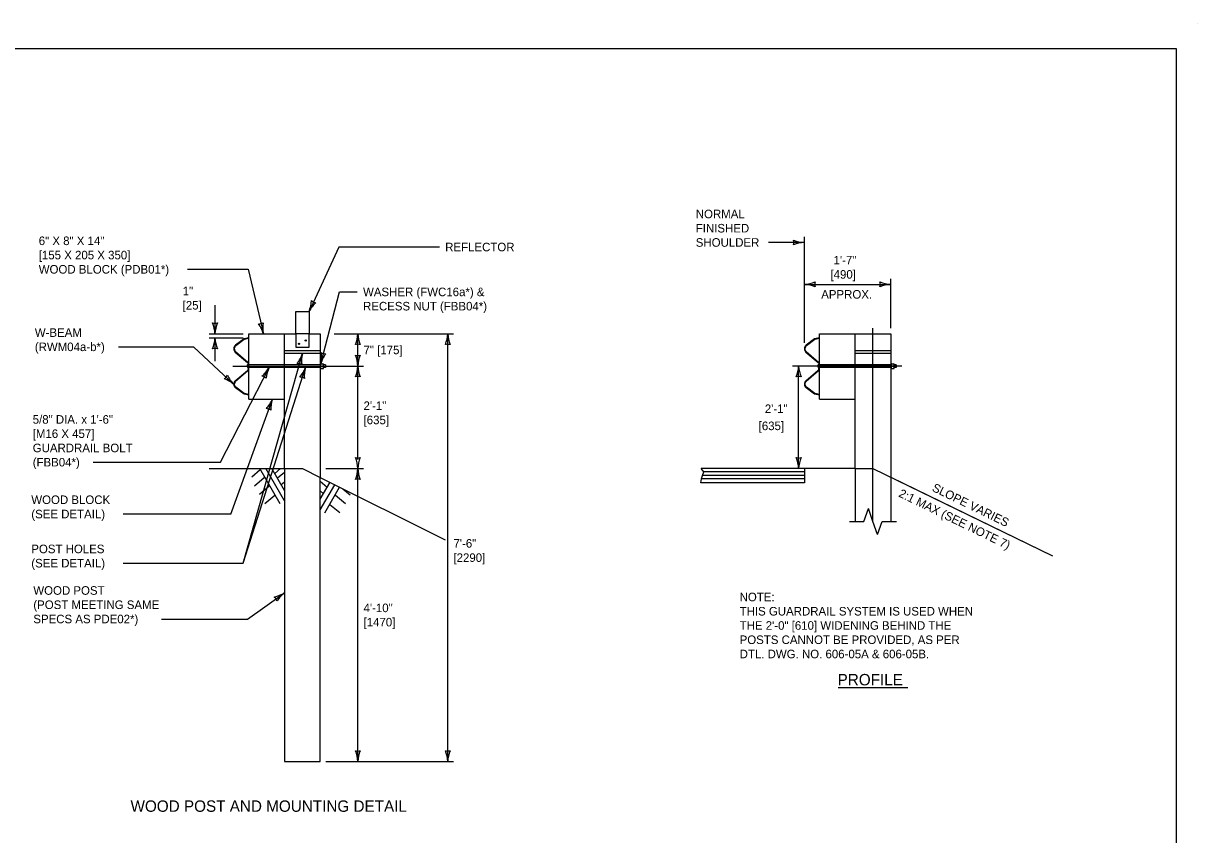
# Model space of a CAD drawing. Extents: x 49991.4 to 50021, y 49987.6 to 50011.4.
# Drawn here: x 50008.67 to 50016.9, y 49993.49 to 49999.18 of the extents above; entities that cross this region are included whole.
import ezdxf

# ---------------------------------------------------------------- set-up
doc = ezdxf.new("R2010")
doc.units = 0
for name, color, linetype in [('Level 1', 7, 'Continuous'), ('Level 2', 7, 'Continuous'), ('Level 3', 7, 'Continuous'), ('Level 4', 7, 'Continuous'), ('Level 5', 7, 'Continuous'), ('Level 6', 7, 'Continuous')]:
    doc.layers.add(name, color=color, linetype=linetype)

msp = doc.modelspace()

# ---------------------------------------------------------------- linework, layer by layer
at = {"layer": 'Level 1'}
for p, q in [((50016.9001, 49999.1756), (50016.9001, 49999.1756)), ((50010.2499, 49996.9992), (50010.5781, 49996.9992)), ((50010.2499, 49996.5402), (50010.2499, 49996.9992)), ((50010.5, 49996.0543), (50010.5, 49996.9992)), ((50010.5781, 49996.9992), (50010.5781, 49996.9054)), ((50010.6717, 49996.9992), (50010.7501, 49996.9992)), ((50010.6717, 49996.9054), (50010.6717, 49996.9992)), ((50010.7501, 49996.9992), (50010.7501, 49995.9918)), ((50014.2499, 49996.9992), (50014.7501, 49996.9992)), ((50014.2499, 49996.5402), (50014.2499, 49996.9992)), ((50014.5, 49996.0543), (50014.5, 49996.9992)), ((50014.7501, 49996.9992), (50014.7501, 49995.9933)), ((50010.2159, 49996.9635), (50010.1562, 49996.9189)), ((50010.2175, 49996.9599), (50010.1585, 49996.9158)), ((50010.2499, 49996.9697), (50010.2159, 49996.9635)), ((50010.2499, 49996.9655), (50010.2175, 49996.9599)), ((50014.2159, 49996.9635), (50014.1562, 49996.9189)), ((50014.2175, 49996.9599), (50014.1585, 49996.9158)), ((50014.2499, 49996.9697), (50014.2159, 49996.9635)), ((50014.2499, 49996.9655), (50014.2175, 49996.9599)), ((50010.1545, 49996.8711), (50010.2396, 49996.7969)), ((50010.157, 49996.874), (50010.2421, 49996.7999)), ((50010.5781, 49996.9054), (50010.6717, 49996.9054)), ((50014.1545, 49996.8711), (50014.2396, 49996.7969)), ((50014.157, 49996.874), (50014.2421, 49996.7999)), ((50010.248, 49996.7727), (50010.2382, 49996.7727)), ((50010.7501, 49996.7931), (50010.752, 49996.7931)), ((50010.7501, 49996.752), (50010.752, 49996.752)), ((50010.752, 49996.7931), (50010.752, 49996.752)), ((50010.752, 49996.7892), (50010.7736, 49996.7892)), ((50010.752, 49996.7727), (50010.7736, 49996.7727)), ((50010.752, 49996.7562), (50010.7736, 49996.7562)), ((50010.7736, 49996.7562), (50010.7736, 49996.7892)), ((50010.7867, 49996.7823), (50010.7736, 49996.7823)), ((50010.7867, 49996.7629), (50010.7736, 49996.7629)), ((50010.7867, 49996.7823), (50010.7867, 49996.7629)), ((50014.248, 49996.7727), (50014.2382, 49996.7727)), ((50014.7501, 49996.7931), (50014.752, 49996.7931)), ((50014.7501, 49996.752), (50014.752, 49996.752)), ((50014.752, 49996.7931), (50014.752, 49996.752)), ((50014.752, 49996.7892), (50014.7736, 49996.7892)), ((50014.752, 49996.7727), (50014.7736, 49996.7727)), ((50014.752, 49996.7562), (50014.7736, 49996.7562)), ((50014.7736, 49996.7562), (50014.7736, 49996.7892)), ((50014.7867, 49996.7823), (50014.7736, 49996.7823)), ((50014.7867, 49996.7629), (50014.7736, 49996.7629)), ((50014.7867, 49996.7823), (50014.7867, 49996.7629)), ((50010.1545, 49996.6687), (50010.2393, 49996.7426)), ((50010.157, 49996.6657), (50010.2435, 49996.7411)), ((50014.1545, 49996.6687), (50014.2393, 49996.7426)), ((50014.157, 49996.6657), (50014.2435, 49996.7411)), ((50010.2159, 49996.5756), (50010.1562, 49996.6209)), ((50010.2175, 49996.5794), (50010.1585, 49996.624)), ((50014.2159, 49996.5756), (50014.1562, 49996.6209)), ((50014.2175, 49996.5794), (50014.1585, 49996.624)), ((50010.2499, 49996.5697), (50010.2159, 49996.5756)), ((50010.2499, 49996.5737), (50010.2175, 49996.5794)), ((50010.2499, 49996.5402), (50010.5, 49996.5402)), ((50014.2499, 49996.5697), (50014.2159, 49996.5756)), ((50014.2499, 49996.5737), (50014.2175, 49996.5794)), ((50014.2499, 49996.5402), (50014.5, 49996.5402)), ((50009.9723, 49996.0543), (50010.5, 49996.0543)), ((50010.3302, 49996.0448), (50010.2697, 49995.994)), ((50010.4687, 49995.8067), (50010.326, 49996.0543)), ((50010.5, 49995.8269), (50010.3687, 49996.0543)), ((50010.5, 49995.9006), (50010.4113, 49996.0543)), ((50010.4712, 49996.0543), (50010.4309, 49996.0204)), ((50010.5, 49996.0273), (50010.4517, 49995.9867)), ((50014.5, 49996.0543), (50013.4216, 49996.0543)), ((50013.4398, 49996.0303), (50013.4216, 49996.0543)), ((50013.4308, 49996.0063), (50013.4398, 49996.0303)), ((50014.1439, 49996.0303), (50013.4398, 49996.0303)), ((50014.1439, 49996.0543), (50014.1439, 49995.9544)), ((50010.3581, 49995.9889), (50010.2895, 49995.9313)), ((50010.3932, 49995.9307), (50010.3238, 49995.8725)), ((50010.5, 49995.9591), (50010.4774, 49995.94)), ((50010.7501, 49995.9918), (50011.6251, 49995.5543)), ((50010.7501, 49995.9648), (50010.7983, 49995.9242)), ((50010.7501, 49995.8381), (50010.8189, 49995.9574)), ((50010.7501, 49995.7643), (50010.8519, 49995.9409)), ((50013.418, 49995.9544), (50013.4226, 49995.9823)), ((50014.1439, 49995.9544), (50013.418, 49995.9544)), ((50013.4226, 49995.9823), (50013.4308, 49996.0063)), ((50014.1439, 49995.9823), (50013.4226, 49995.9823)), ((50014.1439, 49996.0063), (50013.4308, 49996.0063)), ((50014.7501, 49995.9933), (50015.8828, 49995.4409)), ((50010.4316, 49995.8654), (50010.3622, 49995.8072)), ((50010.7501, 49995.8966), (50010.7726, 49995.8775)), ((50010.7814, 49995.7442), (50010.8852, 49995.9242)), ((50010.8569, 49995.8682), (50010.9262, 49995.81)), ((50010.9081, 49995.9128), (50010.9605, 49995.8688)), ((50010.8185, 49995.8029), (50010.8878, 49995.7447))]:
    msp.add_line(p, q, dxfattribs=at)
for points in [[(49999.3835, 49998.9992), (50016.7501, 49998.9992), (50016.7501, 49987.7988), (49999.3835, 49987.7988)], [(50010.5781, 49997.1554), (50010.6717, 49997.1554), (50010.6717, 49996.9992), (50010.5781, 49996.9992)]]:
    msp.add_lwpolyline(points, close=True, dxfattribs=at)
for centre in [(50010.6015, 49996.9287), (50010.6483, 49996.9521)]:
    msp.add_circle(centre, 0.0039, dxfattribs=at)
for centre, radius, start, end in [((50010.1747, 49996.8943), 0.0308, 126.89692, 228.93931), ((50010.1747, 49996.8943), 0.0269, 126.89692, 228.93931), ((50014.1747, 49996.8943), 0.0308, 126.89692, 228.93931), ((50014.1747, 49996.8943), 0.0269, 126.89692, 228.93931), ((50010.2195, 49996.7659), 0.0306, 310.4718, 354.09773), ((50010.2195, 49996.7738), 0.0306, 5.90227, 48.93931), ((50010.2195, 49996.7738), 0.0345, 28.10432, 48.93931), ((50010.2195, 49996.7659), 0.0345, 314.1015, 331.89568), ((50014.2195, 49996.7659), 0.0306, 310.4718, 354.09773), ((50014.2195, 49996.7738), 0.0306, 5.90227, 48.93931), ((50014.2195, 49996.7738), 0.0345, 28.10432, 48.93931), ((50014.2195, 49996.7659), 0.0345, 314.1015, 331.89568), ((50010.1747, 49996.6455), 0.0308, 131.06069, 233.10308), ((50014.1747, 49996.6455), 0.0308, 131.06069, 233.10308), ((50010.1747, 49996.6455), 0.0269, 131.06069, 233.10308), ((50014.1747, 49996.6455), 0.0269, 131.06069, 233.10308)]:
    msp.add_arc(centre, radius, start, end, dxfattribs=at)
for centre, major_axis, ratio, start_param, end_param in [((50010.2479, 49996.7725), (0, 0.0146), 0.663267, 0.091019, 3.253139), ((50010.7651, 49996.781), (0.00829, 0.00104), 0.990733, 4.594607, 7.611796), ((50010.7651, 49996.7644), (-0.00829, -0.00104), 0.990733, 1.560784, 4.582629), ((50014.2479, 49996.7725), (0, 0.0146), 0.663267, 0.091019, 3.253139), ((50014.7651, 49996.781), (0.00829, 0.00104), 0.990733, 4.594607, 7.611796), ((50014.7651, 49996.7644), (-0.00829, -0.00104), 0.990733, 1.560784, 4.582629)]:
    msp.add_ellipse(centre, major_axis=major_axis, ratio=ratio, start_param=start_param, end_param=end_param, dxfattribs=at)
at = {"layer": 'Level 2'}
msp.add_line((50014.3805, 49994.5174), (50014.8696, 49994.5174), dxfattribs=at)
at = {"layer": 'Level 3'}
for p, q in [((50014.1439, 49996.9354), (50014.1439, 49997.6796)), ((50010.8808, 49997.6076), (50010.6717, 49997.1554)), ((50011.5862, 49997.6076), (50010.8808, 49997.6076)), ((50014.1439, 49997.6396), (50013.8931, 49997.6396)), ((50009.8185, 49997.4513), (50010.2443, 49997.4513)), ((50010.2443, 49997.4513), (50010.3514, 49996.9992)), ((50014.1439, 49997.3457), (50014.7501, 49997.3457)), ((50014.7501, 49997.0392), (50014.7501, 49997.3857)), ((50010.7536, 49996.7892), (50010.8854, 49997.2929)), ((50010.8854, 49997.2929), (50011.0102, 49997.2929)), ((50010.0123, 49997.1992), (50010.0123, 49996.9992)), ((50009.9723, 49996.9992), (50010.2099, 49996.9992)), ((50010.8485, 49996.9992), (50011.6841, 49996.9992)), ((50011.0138, 49996.7727), (50011.0138, 49996.9992)), ((50011.6441, 49993.9992), (50011.6441, 49996.9992)), ((50009.9723, 49996.9697), (50010.2099, 49996.9697)), ((50010.0123, 49996.9697), (50010.0123, 49996.8068)), ((50009.3371, 49996.9077), (50009.8611, 49996.9077)), ((50009.8611, 49996.9077), (50010.1439, 49996.6443)), ((50010.2091, 49995.3904), (50010.6251, 49996.86)), ((50010.0502, 49996.0985), (50010.3914, 49996.7629)), ((50010.2091, 49995.3904), (50010.6463, 49996.7629)), ((50011.0138, 49996.1167), (50011.0138, 49996.7727)), ((50014.1039, 49996.0543), (50014.1039, 49996.7726)), ((50010.1237, 49995.7351), (50010.4144, 49996.5402)), ((50009.1585, 49996.0985), (50010.0502, 49996.0985)), ((50010.7901, 49996.0543), (50011.0538, 49996.0543)), ((50011.0138, 49993.9992), (50011.0138, 49996.0543)), ((50010.1237, 49995.7351), (50009.3685, 49995.7351)), ((50009.3685, 49995.3904), (50010.2091, 49995.3904)), ((50010.2396, 49994.9988), (50010.5, 49995.1833)), ((50009.6384, 49994.9988), (50010.2396, 49994.9988)), ((50010.7901, 49993.9992), (50011.6841, 49993.9992))]:
    msp.add_line(p, q, dxfattribs=at)
for centre, radius, start, end in [((50014.0157, 49997.6396), 0.0548, 342.13882, 17.86118), ((50014.1554, 49997.8723), 0.233, 247.92284, 267.17269), ((50014.1531, 49997.4175), 0.2223, 92.36048, 112.54399), ((50014.1324, 49997.5784), 0.233, 272.82731, 292.07716), ((50014.1348, 49997.1236), 0.2223, 67.45601, 87.63952), ((50014.2721, 49997.3457), 0.0548, 162.13882, 197.86118), ((50014.7593, 49997.5678), 0.2223, 247.45601, 267.63952), ((50014.6219, 49997.3457), 0.0548, 342.13882, 17.86118), ((50014.7616, 49997.113), 0.233, 92.82731, 112.07716), ((50010.4557, 49997.2426), 0.233, 338.01864, 357.26849), ((50010.8695, 49997.0539), 0.2223, 132.64734, 152.83085), ((50010.7255, 49997.2718), 0.0548, 227.33015, 263.05251), ((50010.0123, 49997.1274), 0.0548, 252.13882, 287.86118), ((50009.7796, 49996.9877), 0.233, 2.82731, 22.07716), ((50010.2345, 49996.99), 0.2223, 157.45601, 177.63952), ((50010.3219, 49997.1239), 0.0548, 265.4637, 301.18606), ((50010.1276, 49996.9343), 0.233, 16.15219, 35.40204), ((50010.5697, 49997.0414), 0.2223, 170.78089, 190.9644), ((50010.7917, 49997.0084), 0.2223, 337.45601, 357.63952), ((50011.2465, 49997.0107), 0.233, 182.82731, 202.07716), ((50011.422, 49997.0084), 0.2223, 337.45601, 357.63952), ((50011.8768, 49997.0107), 0.233, 182.82731, 202.07716), ((50009.7796, 49996.9811), 0.233, 337.92284, 357.17269), ((50010.2345, 49996.9788), 0.2223, 182.36048, 202.54399), ((50011.0138, 49996.871), 0.0548, 72.13882, 107.86118), ((50011.6441, 49996.871), 0.0548, 72.13882, 107.86118), ((50010.0123, 49996.8414), 0.0548, 72.13882, 107.86118), ((50010.4041, 49996.934), 0.233, 322.22464, 341.47449), ((50010.8414, 49996.8087), 0.2223, 166.66228, 186.84579), ((50010.5255, 49996.837), 0.233, 348.16106, 7.41091), ((50010.9662, 49996.7241), 0.2223, 142.78976, 162.97327), ((50010.786, 49996.9132), 0.0548, 237.47257, 273.19493), ((50011.0138, 49996.9009), 0.0548, 252.13882, 287.86118), ((50010.7811, 49996.7612), 0.233, 2.82731, 22.07716), ((50011.2359, 49996.7636), 0.2223, 157.45601, 177.63952), ((50010.1896, 49996.8794), 0.233, 310.7387, 329.98855), ((50010.5932, 49996.6696), 0.2223, 155.17634, 175.35985), ((50010.5904, 49996.7365), 0.0548, 56.44062, 92.16298), ((50010.4376, 49996.8395), 0.2223, 319.67231, 339.85582), ((50010.8714, 49996.7028), 0.233, 165.04361, 184.29346), ((50010.7917, 49996.7819), 0.2223, 337.45601, 357.63952), ((50011.2465, 49996.7842), 0.233, 182.82731, 202.07716), ((50013.8818, 49996.7818), 0.2223, 337.45601, 357.63952), ((50014.3366, 49996.7841), 0.233, 182.82731, 202.07716), ((50010.0501, 49996.7317), 0.0548, 299.18069, 334.90305), ((50009.9992, 49996.4755), 0.2223, 49.40235, 69.58586), ((50010.3109, 49996.8068), 0.233, 204.96471, 224.21456), ((50010.3328, 49996.6489), 0.0548, 44.95468, 80.67704), ((50010.6071, 49996.6408), 0.0548, 54.35512, 90.07748), ((50011.0138, 49996.6445), 0.0548, 72.13882, 107.86118), ((50014.1039, 49996.6444), 0.0548, 72.13882, 107.86118), ((50010.1994, 49996.63), 0.233, 318.07314, 337.32299), ((50010.6264, 49996.4734), 0.2223, 162.51078, 182.69429), ((50010.3708, 49996.4196), 0.0548, 52.28912, 88.01148), ((50011.0138, 49996.1825), 0.0548, 252.13882, 287.86118), ((50010.7811, 49996.0428), 0.233, 2.82731, 22.07716), ((50011.2359, 49996.0452), 0.2223, 157.45601, 177.63952), ((50014.1039, 49996.1825), 0.0548, 252.13882, 287.86118), ((50013.8712, 49996.0428), 0.233, 2.82731, 22.07716), ((50014.3261, 49996.0452), 0.2223, 157.45601, 177.63952), ((50010.7917, 49996.0635), 0.2223, 337.45601, 357.63952), ((50011.2465, 49996.0658), 0.233, 182.82731, 202.07716), ((50011.0138, 49995.9261), 0.0548, 72.13882, 107.86118), ((50010.3791, 49995.3698), 0.2223, 282.76822, 302.95173), ((50010.3954, 49995.1092), 0.0548, 17.45103, 53.17339), ((50010.6439, 49995), 0.233, 128.13952, 147.38937), ((50011.0138, 49994.1274), 0.0548, 252.13882, 287.86118), ((50010.7811, 49993.9877), 0.233, 2.82731, 22.07716), ((50011.2359, 49993.99), 0.2223, 157.45601, 177.63952), ((50011.6441, 49994.1274), 0.0548, 252.13882, 287.86118), ((50011.4114, 49993.9877), 0.233, 2.82731, 22.07716), ((50011.8662, 49993.99), 0.2223, 157.45601, 177.63952)]:
    msp.add_arc(centre, radius, start, end, dxfattribs=at)
at = {"layer": 'Level 4'}
for p, q in [((50010.7501, 49996.8794), (50010.5, 49996.8794)), ((50010.7501, 49996.86), (50010.5, 49996.86)), ((50014.7501, 49996.8794), (50014.5, 49996.8794)), ((50014.7501, 49996.86), (50014.5, 49996.86)), ((50010.7501, 49996.7823), (50010.2499, 49996.7823)), ((50010.7501, 49996.7629), (50010.2499, 49996.7629)), ((50014.7501, 49996.7823), (50014.2499, 49996.7823)), ((50014.7501, 49996.7629), (50014.2499, 49996.7629)), ((50010.5, 49996.0543), (50010.5, 49993.9992)), ((50010.5, 49996.0543), (50010.6251, 49996.0543)), ((50010.6251, 49996.0543), (50010.7501, 49995.9918)), ((50014.5, 49996.0543), (50014.5, 49995.6835)), ((50014.5, 49996.0543), (50014.6251, 49996.0543)), ((50014.6251, 49996.0543), (50015.8828, 49995.4409)), ((50010.7501, 49993.9992), (50010.7501, 49995.9918)), ((50014.7501, 49995.9933), (50014.7501, 49995.6846)), ((50010.5, 49993.9992), (50010.7501, 49993.9992))]:
    msp.add_line(p, q, dxfattribs=at)
at = {"layer": 'Level 5'}
for p, q in [((50014.6251, 49995.6835), (50014.6251, 49997.0392)), ((50010.1382, 49996.7727), (50011.0538, 49996.7727)), ((50014.8267, 49996.7726), (50014.0618, 49996.7726))]:
    msp.add_line(p, q, dxfattribs=at)
at = {"layer": 'Level 6'}
for p, q in [((50014.5603, 49995.6835), (50014.5927, 49995.7749)), ((50014.6251, 49995.6835), (50014.5927, 49995.7749)), ((50014.46, 49995.6835), (50014.5603, 49995.6835)), ((50014.6575, 49995.5921), (50014.6251, 49995.6835)), ((50014.6575, 49995.5921), (50014.6899, 49995.6835)), ((50014.6899, 49995.6835), (50014.7907, 49995.6835))]:
    msp.add_line(p, q, dxfattribs=at)

# ---------------------------------------------------------------- texts
at = {"layer": 'Level 2'}
for s, height, p in [('NORMAL', 0.06, (50013.3828, 49997.8096)), ('FINISHED', 0.06, (50013.3828, 49997.7096)), ('6" X 8" X 14"', 0.06, (50008.7769, 49997.6213)), ('SHOULDER', 0.06, (50013.3828, 49997.6096)), ('[155 X 205 X 350]', 0.06, (50008.7769, 49997.5213)), ('REFLECTOR', 0.06, (50011.6262, 49997.5776)), ('1\'-7"', 0.06, (50014.3487, 49997.4857)), ('WOOD BLOCK (PDB01*)', 0.06, (50008.7769, 49997.4213)), ('[490]', 0.06, (50014.3269, 49997.3857)), ('1"', 0.06, (50009.7858, 49997.2692)), ('WASHER (FWC16a*) &', 0.06, (50011.0502, 49997.2629)), ('APPROX.', 0.06, (50014.2622, 49997.2457)), ('[25]', 0.06, (50009.7858, 49997.1692)), ('RECESS NUT (FBB04*)', 0.06, (50011.0502, 49997.1629)), ('W-BEAM', 0.06, (50008.7494, 49996.9777)), ('(RWM04a-b*)', 0.06, (50008.7494, 49996.8777)), ('7" [175]', 0.06, (50011.0538, 49996.856)), ('2\'-1"', 0.06, (50011.0538, 49996.4647)), ('2\'-1"', 0.06, (50013.867, 49996.4435)), ('5/8" DIA. x 1\'-6"', 0.06, (50008.7346, 49996.3685)), ('[635]', 0.06, (50011.0538, 49996.3647)), ('[635]', 0.06, (50013.8235, 49996.3235)), ('[M16 X 457]', 0.06, (50008.7346, 49996.2685)), ('GUARDRAIL BOLT', 0.06, (50008.7346, 49996.1685)), ('(FBB04*)', 0.06, (50008.7346, 49996.0685)), ('WOOD BLOCK', 0.06, (50008.7247, 49995.8051)), ('(SEE DETAIL)', 0.06, (50008.7247, 49995.7051)), ('POST HOLES', 0.06, (50008.7247, 49995.4604)), ('7\'-6" ', 0.06, (50011.6841, 49995.4992)), ('[2290]', 0.06, (50011.6841, 49995.3992)), ('(SEE DETAIL)', 0.06, (50008.7247, 49995.3604)), ('WOOD POST', 0.06, (50008.7389, 49995.1688)), ('(POST MEETING SAME ', 0.06, (50008.7389, 49995.0688)), ('4\'-10" ', 0.06, (50011.0538, 49995.0468)), ('NOTE:', 0.06, (50013.6903, 49995.1233)), ('SPECS AS PDE02*)', 0.06, (50008.7389, 49994.9688)), ('THIS GUARDRAIL SYSTEM IS USED WHEN', 0.06, (50013.6903, 49995.0233)), ('[1470]', 0.06, (50011.0538, 49994.9468)), ('THE 2\'-0" [610] WIDENING BEHIND THE', 0.06, (50013.6903, 49994.9233)), ('POSTS CANNOT BE PROVIDED, AS PER ', 0.06, (50013.6903, 49994.8233)), ('DTL. DWG. NO. 606-05A & 606-05B.', 0.06, (50013.6903, 49994.7233)), ('PROFILE', 0.08, (50014.3769, 49994.5334)), ('WOOD POST AND MOUNTING DETAIL', 0.08, (50009.4203, 49993.6465))]:
    msp.add_text(s, height=height, dxfattribs=at).set_placement(p)
for s, p in [('SLOPE VARIES', (50015.0343, 49995.8992)), ('2:1 MAX (SEE NOTE 7)', (50014.7999, 49995.8597))]:
    msp.add_text(s, height=0.06, rotation=334.00293, dxfattribs=at).set_placement(p)

doc.saveas('drawing.dxf')
